Omron CX-Programmer project NewProject (CX-Programmer 9.65)

# PLC ParkerP2MExample: CJ2M CPU31
; Example Program For Parker P2M EtherNet/IP
I/O table (CPU CJ2M-CPU31): rack 0 slot 11 CJ2M-EIP21

## Global symbols (name address type ; comment)
W31.03 BOOL  ; Wr Clear Cycle Counters
W30.07 BOOL  ; Rd Output Behavior
1520.10 BOOL  ; EtherNet/IP Comm OK
A202.00 BOOL  ; Communications Port Enabled Flag (Port 0)
D0 CHANNEL  ; Node ID (Last Octet)
D1 CHANNEL  ; Class ID
D10 CHANNEL  ; Number of Bytes To Receive
D11 CHANNEL  ; Byte Order & Unit #
D12 CHANNEL  ; Response Monitor Time
D13 CHANNEL  ; Explicit Message Format
D150 CHANNEL  ; Byte Order & Unit #
D151 CHANNEL  ; Response Monitoring Time
D152 CHANNEL  ; Explicit Message Format
D2 CHANNEL  ; Instance ID
D200 CHANNEL  ; # of Bytes To Send (From D201 On)
D201 CHANNEL  ; Node ID
D202 CHANNEL  ; Class ID
D203 CHANNEL  ; Instance ID
D204 CHANNEL  ; Attribute ID
D205 CHANNEL  ; Write Data
D3 CHANNEL  ; Attribute ID
D300 CHANNEL  ; Aux Volt Lo Lim
D301 CHANNEL  ; Aux Volt Hi Lim
D302 CHANNEL  ; Output Behavior On Comm Loss
D304 CHANNEL  ; Solenoids 1-16 Clear Cycle Counter Bits
D305 CHANNEL  ; Solenoids 17-24 Clear Cycle Counter Bits
W0.00 BOOL  ; Acknowledge Required
W0.01 BOOL  ; Auxiliary Voltage Warning
W0.02 BOOL  ; Auxiliary Voltage Failure
W0.03 BOOL  ; Temperature Warning
W0.04 BOOL  ; Output Driver Channel Error
W0.05 BOOL  ; Module Error
W0.06 BOOL  ; Output Stages Not Available
W100 CHANNEL  ; Sys Command / Sol 1-8
W100.00 BOOL  ; Sys Cmd - Leave Fail State
W100.01 BOOL  ; Sys Cmd - Store Cycle Counters
W100.08 BOOL  ; Solenoid 1
W100.09 BOOL  ; Solenoid 2
W100.10 BOOL  ; Solenoid 3
W100.11 BOOL  ; Solenoid 4
W100.12 BOOL  ; Solenoid 5
W100.13 BOOL  ; Solenoid 6
W100.14 BOOL  ; Solenoid 7
W100.15 BOOL  ; Solenoid 8
W101 CHANNEL  ; Solenoids 9-24
W101.00 BOOL  ; Solenoid 9
W101.01 BOOL  ; Solenoid 10
W101.02 BOOL  ; Solenoid 11
W101.03 BOOL  ; Solenoid 12
W101.04 BOOL  ; Solenoid 13
W101.05 BOOL  ; Solenoid 14
W101.06 BOOL  ; Solenoid 15
W101.07 BOOL  ; Solenoid 16
W101.08 BOOL  ; Solenoid 17
W101.09 BOOL  ; Solenoid 18
W101.10 BOOL  ; Solenoid 19
W101.11 BOOL  ; Solenoid 20
W101.12 BOOL  ; Solenoid 21
W101.13 BOOL  ; Solenoid 22
W101.14 BOOL  ; Solenoid 23
W101.15 BOOL  ; Solenoid 24
W11.00 BOOL  ; Connection Error
W11.01 BOOL  ; Read Command Enabled
W11.02 BOOL  ; Write Command Enabled
W200.00 BOOL  ; Leave Fail Safe State
W200.01 BOOL  ; Store Cycle Counts
W20.08 BOOL  ; Fire EV01
W20.09 BOOL  ; Fire EV02
W21.00 BOOL  ; Fire EV09
W21.01 BOOL  ; Fire EV10
W25.00 BOOL  ; Fault Present
W30 CHANNEL  ; Read Commands
W30.00 BOOL  ; Read All Parameters
W30.01 BOOL  ; Rd Aux Voltage
W30.02 BOOL  ; Rd Lo Limit
W30.03 BOOL  ; Rd Hi Limit
W30.04 BOOL  ; Rd Cycle Counters
W30.05 BOOL  ; Rd Channel Errors
W30.06 BOOL  ; Rd Module Info
W31 CHANNEL  ; Write Command Enabled
W31.00 BOOL  ; Wr Aux Volt Lo Lim
W31.01 BOOL  ; Wr Aux Volt Hi Lim
W31.02 BOOL  ; Wr Output Behavior

## Program NewProgram1 (cyclic task 0)

### Section P2M2HBVE

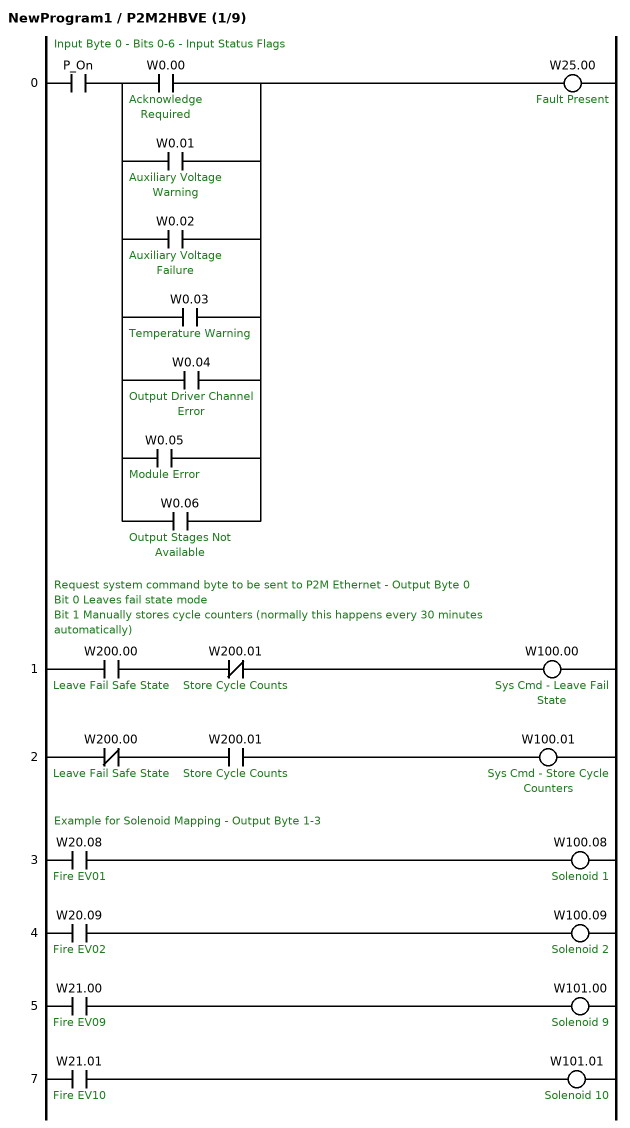
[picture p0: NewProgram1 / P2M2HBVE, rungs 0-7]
; rung 0: Input Byte 0 - Bits 0-6 - Input Status Flags
LD P_On
LD W0.00  ; Acknowledge Required
OR W0.01  ; Auxiliary Voltage Warning
OR W0.02  ; Auxiliary Voltage Failure
OR W0.03  ; Temperature Warning
OR W0.04  ; Output Driver Channel Error
OR W0.05  ; Module Error
OR W0.06  ; Output Stages Not Available
ANDLD
OUT W25.00  ; Fault Present
; rung 1: Request system command byte to be sent to P2M Ethernet - Output Byte 0 / Bit 0 Leaves fail state mode / Bit 1 Manually stores cycle counters (normally this happens every 30 minutes automatically)
LD W200.00  ; Leave Fail Safe State
ANDNOT W200.01  ; Store Cycle Counts
OUT W100.00  ; Sys Cmd - Leave Fail State
; rung 2
LDNOT W200.00  ; Leave Fail Safe State
AND W200.01  ; Store Cycle Counts
OUT W100.01  ; Sys Cmd - Store Cycle Counters
; rung 3: Example for Solenoid Mapping - Output Byte 1-3
LD W20.08  ; Fire EV01
OUT W100.08  ; Solenoid 1
; rung 4
LD W20.09  ; Fire EV02
OUT W100.09  ; Solenoid 2
; rung 5
LD W21.00  ; Fire EV09
OUT W101.00  ; Solenoid 9
; rung 7
LD W21.01  ; Fire EV10
OUT W101.01  ; Solenoid 10

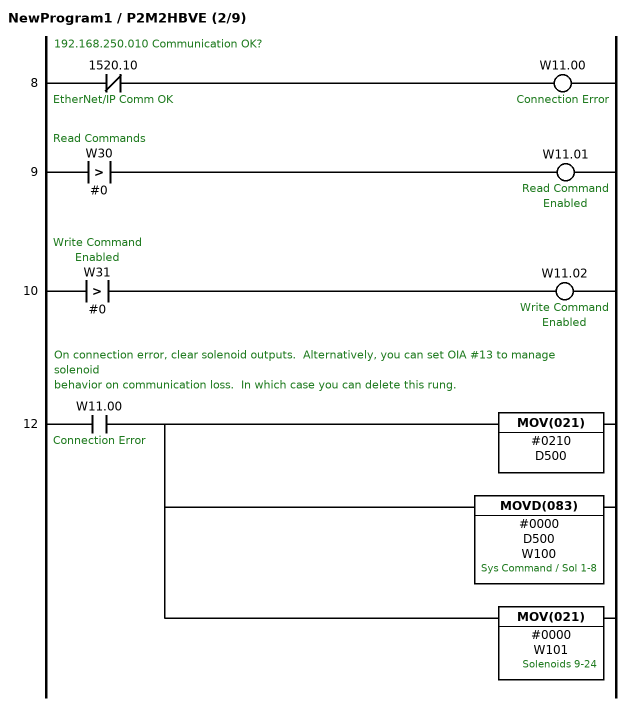
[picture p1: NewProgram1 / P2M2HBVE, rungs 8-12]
; rung 8: 192.168.250.010 Communication OK?
LDNOT 1520.10  ; EtherNet/IP Comm OK
OUT W11.00  ; Connection Error
; rung 9
LD>(320) W30 #0  ; Read Commands
OUT W11.01  ; Read Command Enabled
; rung 10
LD>(320) W31 #0  ; Write Command Enabled
OUT W11.02  ; Write Command Enabled
; rung 12: On connection error, clear solenoid outputs.  Alternatively, you can set OIA #13 to manage solenoid / behavior on communication loss.  In which case you can delete this rung.
LD W11.00  ; Connection Error
MOV(021) #0210 D500
MOVD(083) #0000 D500 W100  ; Sys Command / Sol 1-8
MOV(021) #0000 W101  ; Solenoids 9-24

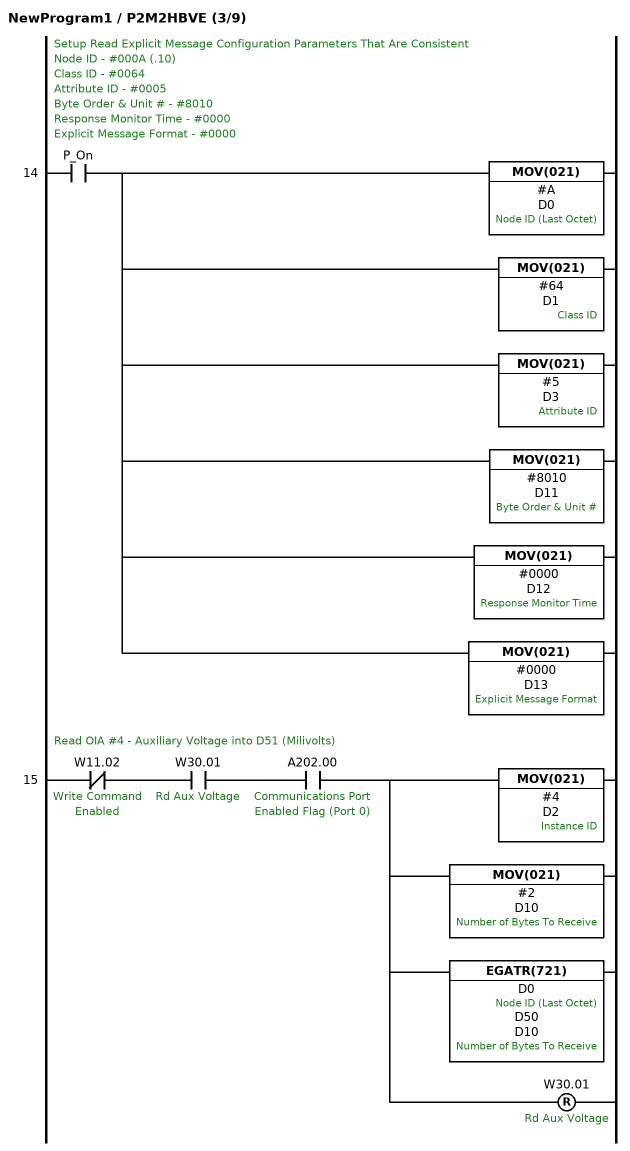
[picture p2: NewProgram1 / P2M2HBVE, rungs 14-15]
; rung 14: Setup Read Explicit Message Configuration Parameters That Are Consistent / Node ID - #000A (.10) / Class ID - #0064 / Attribute ID - #0005 / Byte Order & Unit # - #8010 / Response Monitor Time - #0000 / Explicit Message Format - #0000
LD P_On
MOV(021) #A D0  ; Node ID (Last Octet)
MOV(021) #64 D1  ; Class ID
MOV(021) #5 D3  ; Attribute ID
MOV(021) #8010 D11  ; Byte Order & Unit #
MOV(021) #0000 D12  ; Response Monitor Time
MOV(021) #0000 D13  ; Explicit Message Format
; rung 15: Read OIA #4 - Auxiliary Voltage into D51 (Milivolts)
LDNOT W11.02  ; Write Command Enabled
AND W30.01  ; Rd Aux Voltage
AND A202.00  ; Communications Port Enabled Flag (Port 0)
MOV(021) #4 D2  ; Instance ID
MOV(021) #2 D10  ; Number of Bytes To Receive
EGATR(721) D0 D50 D10  ; Node ID (Last Octet), Number of Bytes To Receive
RSET W30.01  ; Rd Aux Voltage

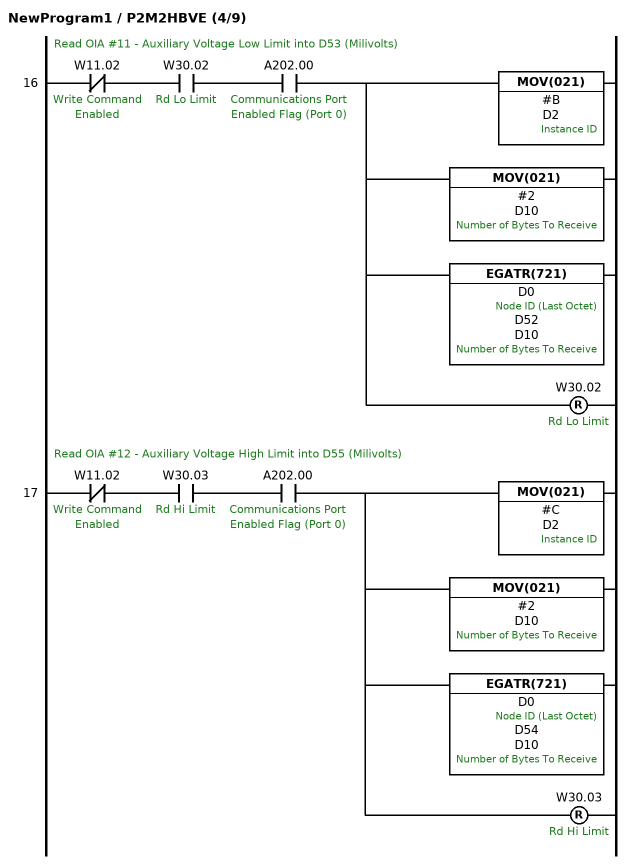
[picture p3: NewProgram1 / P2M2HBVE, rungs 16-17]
; rung 16: Read OIA #11 - Auxiliary Voltage Low Limit into D53 (Milivolts)
LDNOT W11.02  ; Write Command Enabled
AND W30.02  ; Rd Lo Limit
AND A202.00  ; Communications Port Enabled Flag (Port 0)
MOV(021) #B D2  ; Instance ID
MOV(021) #2 D10  ; Number of Bytes To Receive
EGATR(721) D0 D52 D10  ; Node ID (Last Octet), Number of Bytes To Receive
RSET W30.02  ; Rd Lo Limit
; rung 17: Read OIA #12 - Auxiliary Voltage High Limit into D55 (Milivolts)
LDNOT W11.02  ; Write Command Enabled
AND W30.03  ; Rd Hi Limit
AND A202.00  ; Communications Port Enabled Flag (Port 0)
MOV(021) #C D2  ; Instance ID
MOV(021) #2 D10  ; Number of Bytes To Receive
EGATR(721) D0 D54 D10  ; Node ID (Last Octet), Number of Bytes To Receive
RSET W30.03  ; Rd Hi Limit

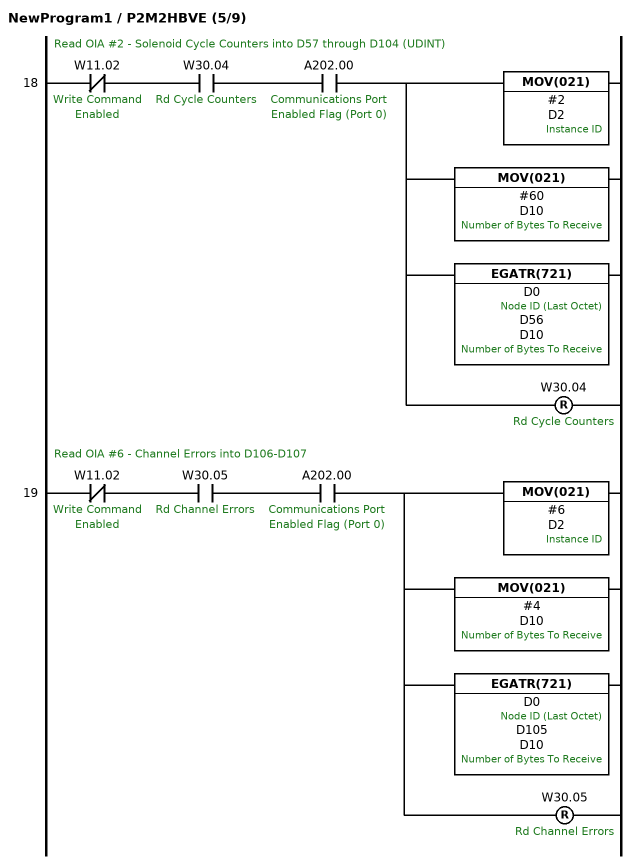
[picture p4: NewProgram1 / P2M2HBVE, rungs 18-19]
; rung 18: Read OIA #2 - Solenoid Cycle Counters into D57 through D104 (UDINT)
LDNOT W11.02  ; Write Command Enabled
AND W30.04  ; Rd Cycle Counters
AND A202.00  ; Communications Port Enabled Flag (Port 0)
MOV(021) #2 D2  ; Instance ID
MOV(021) #60 D10  ; Number of Bytes To Receive
EGATR(721) D0 D56 D10  ; Node ID (Last Octet), Number of Bytes To Receive
RSET W30.04  ; Rd Cycle Counters
; rung 19: Read OIA #6 - Channel Errors into D106-D107
LDNOT W11.02  ; Write Command Enabled
AND W30.05  ; Rd Channel Errors
AND A202.00  ; Communications Port Enabled Flag (Port 0)
MOV(021) #6 D2  ; Instance ID
MOV(021) #4 D10  ; Number of Bytes To Receive
EGATR(721) D0 D105 D10  ; Node ID (Last Octet), Number of Bytes To Receive
RSET W30.05  ; Rd Channel Errors

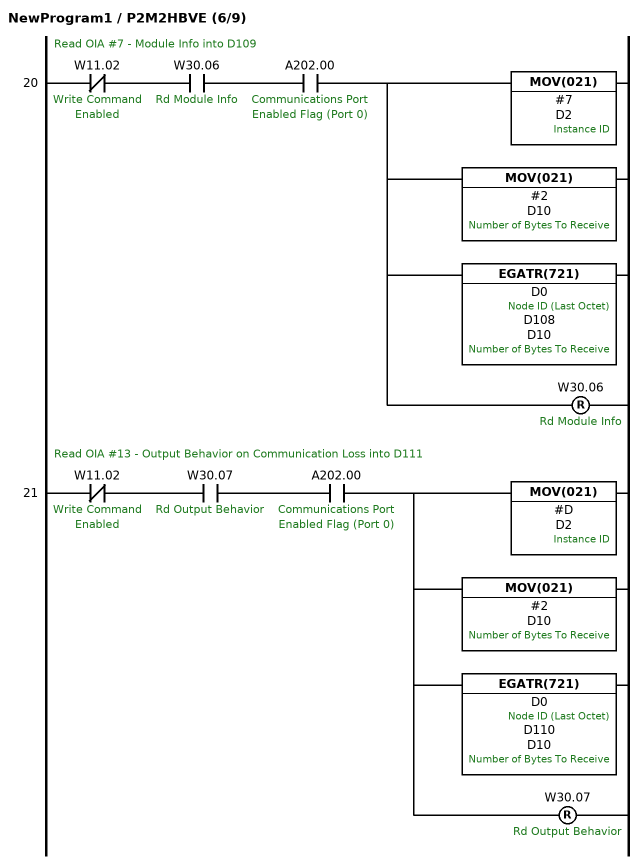
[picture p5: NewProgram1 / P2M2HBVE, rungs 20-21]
; rung 20: Read OIA #7 - Module Info into D109
LDNOT W11.02  ; Write Command Enabled
AND W30.06  ; Rd Module Info
AND A202.00  ; Communications Port Enabled Flag (Port 0)
MOV(021) #7 D2  ; Instance ID
MOV(021) #2 D10  ; Number of Bytes To Receive
EGATR(721) D0 D108 D10  ; Node ID (Last Octet), Number of Bytes To Receive
RSET W30.06  ; Rd Module Info
; rung 21: Read OIA #13 - Output Behavior on Communication Loss into D111
LDNOT W11.02  ; Write Command Enabled
AND W30.07  ; Rd Output Behavior
AND A202.00  ; Communications Port Enabled Flag (Port 0)
MOV(021) #D D2  ; Instance ID
MOV(021) #2 D10  ; Number of Bytes To Receive
EGATR(721) D0 D110 D10  ; Node ID (Last Octet), Number of Bytes To Receive
RSET W30.07  ; Rd Output Behavior

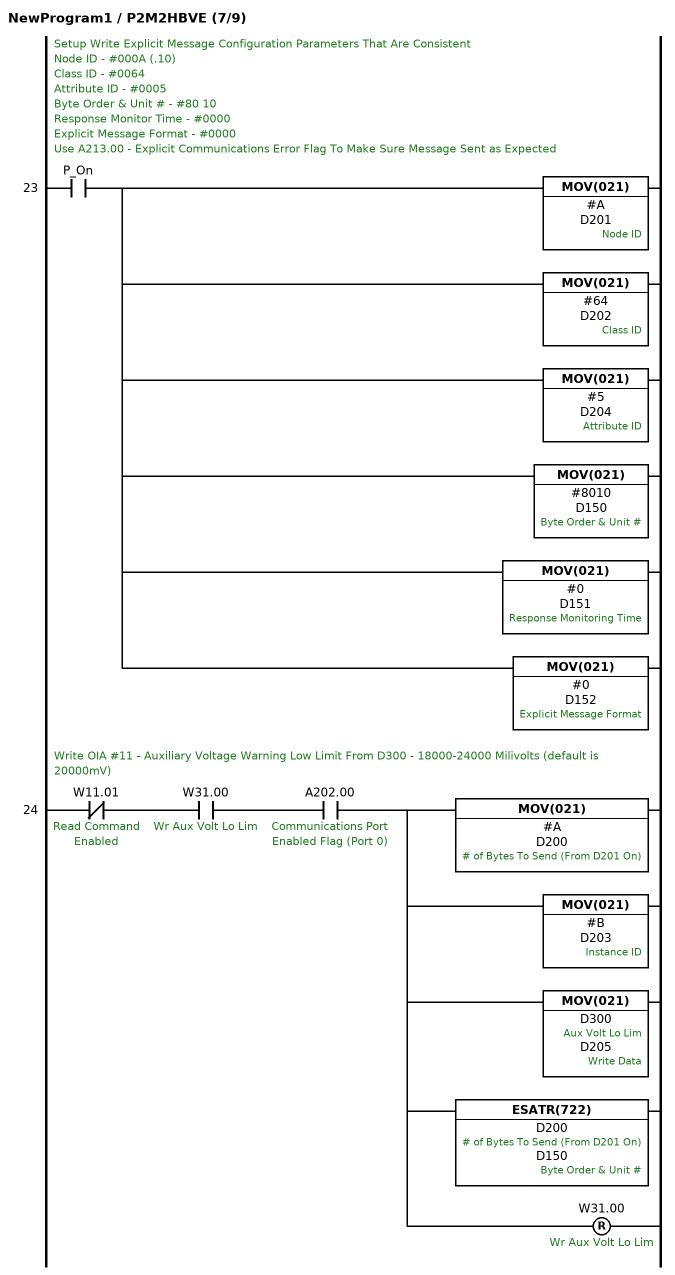
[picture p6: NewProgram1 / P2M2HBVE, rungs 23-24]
; rung 23: Setup Write Explicit Message Configuration Parameters That Are Consistent / Node ID - #000A (.10) / Class ID - #0064 / Attribute ID - #0005 / Byte Order & Unit # - #80 10 / Response Monitor Time - #0000 / Explicit Message Format - #0000 / Use A213.00 - Explicit Communications Error Flag To Make Sure Message Sent as Expected
LD P_On
MOV(021) #A D201  ; Node ID
MOV(021) #64 D202  ; Class ID
MOV(021) #5 D204  ; Attribute ID
MOV(021) #8010 D150  ; Byte Order & Unit #
MOV(021) #0 D151  ; Response Monitoring Time
MOV(021) #0 D152  ; Explicit Message Format
; rung 24: Write OIA #11 - Auxiliary Voltage Warning Low Limit From D300 - 18000-24000 Milivolts (default is 20000mV)
LDNOT W11.01  ; Read Command Enabled
AND W31.00  ; Wr Aux Volt Lo Lim
AND A202.00  ; Communications Port Enabled Flag (Port 0)
MOV(021) #A D200  ; # of Bytes To Send (From D201 On)
MOV(021) #B D203  ; Instance ID
MOV(021) D300 D205  ; Aux Volt Lo Lim, Write Data
ESATR(722) D200 D150  ; # of Bytes To Send (From D201 On), Byte Order & Unit #
RSET W31.00  ; Wr Aux Volt Lo Lim

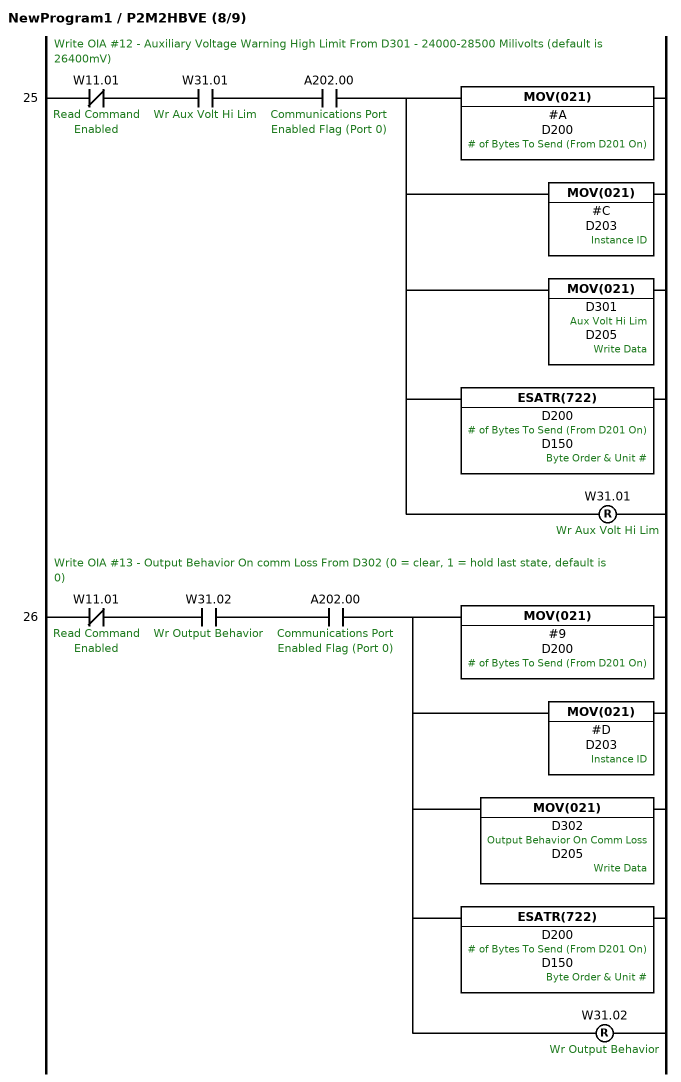
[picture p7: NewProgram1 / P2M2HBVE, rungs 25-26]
; rung 25: Write OIA #12 - Auxiliary Voltage Warning High Limit From D301 - 24000-28500 Milivolts (default is 26400mV)
LDNOT W11.01  ; Read Command Enabled
AND W31.01  ; Wr Aux Volt Hi Lim
AND A202.00  ; Communications Port Enabled Flag (Port 0)
MOV(021) #A D200  ; # of Bytes To Send (From D201 On)
MOV(021) #C D203  ; Instance ID
MOV(021) D301 D205  ; Aux Volt Hi Lim, Write Data
ESATR(722) D200 D150  ; # of Bytes To Send (From D201 On), Byte Order & Unit #
RSET W31.01  ; Wr Aux Volt Hi Lim
; rung 26: Write OIA #13 - Output Behavior On comm Loss From D302 (0 = clear, 1 = hold last state, default is 0)
LDNOT W11.01  ; Read Command Enabled
AND W31.02  ; Wr Output Behavior
AND A202.00  ; Communications Port Enabled Flag (Port 0)
MOV(021) #9 D200  ; # of Bytes To Send (From D201 On)
MOV(021) #D D203  ; Instance ID
MOV(021) D302 D205  ; Output Behavior On Comm Loss, Write Data
ESATR(722) D200 D150  ; # of Bytes To Send (From D201 On), Byte Order & Unit #
RSET W31.02  ; Wr Output Behavior

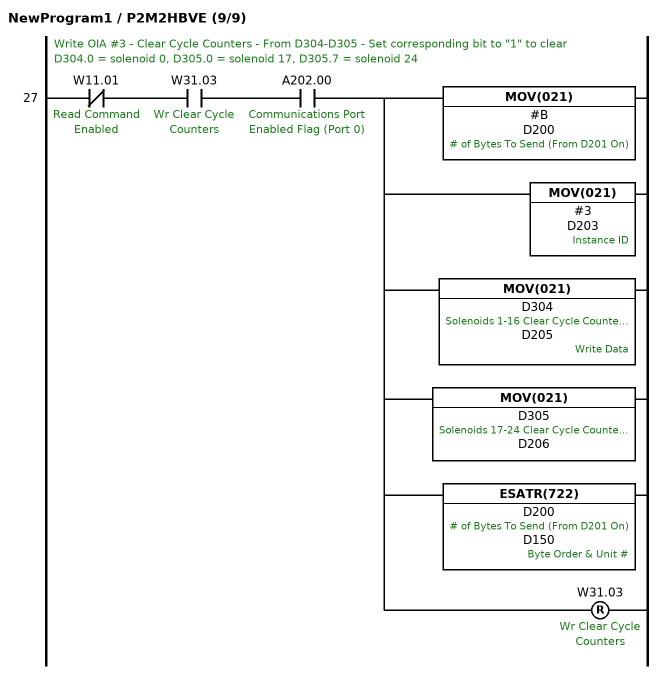
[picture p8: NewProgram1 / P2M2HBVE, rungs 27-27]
; rung 27: Write OIA #3 - Clear Cycle Counters - From D304-D305 - Set corresponding bit to "1" to clear / D304.0 = solenoid 0, D305.0 = solenoid 17, D305.7 = solenoid 24
LDNOT W11.01  ; Read Command Enabled
AND W31.03  ; Wr Clear Cycle Counters
AND A202.00  ; Communications Port Enabled Flag (Port 0)
MOV(021) #B D200  ; # of Bytes To Send (From D201 On)
MOV(021) #3 D203  ; Instance ID
MOV(021) D304 D205  ; Solenoids 1-16 Clear Cycle Counter Bits, Write Data
MOV(021) D305 D206  ; Solenoids 17-24 Clear Cycle Counter Bits
ESATR(722) D200 D150  ; # of Bytes To Send (From D201 On), Byte Order & Unit #
RSET W31.03  ; Wr Clear Cycle Counters

### Section END
; rung 0
END(001)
